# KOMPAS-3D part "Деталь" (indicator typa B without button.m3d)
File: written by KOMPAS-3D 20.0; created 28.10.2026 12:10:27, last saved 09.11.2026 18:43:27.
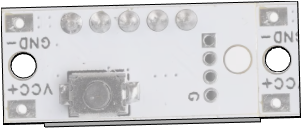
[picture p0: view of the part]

Document properties: Полное имя файла: D:\myProjects\Progect_esp32\box_compas\переключатели и кнопки\indicator typa B without button.m3d

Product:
- Part/product: Деталь
    Масса: 0.00714876

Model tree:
1. Эскиз:1
2. Элемент выдавливания:1
     Расстояние 1 = 1.5
3. Эскиз:2  (with: Элемент выдавливания:1)
4. Элемент выдавливания:2
     Расстояние 2 = 1.5
5. Эскиз:3  (with: Элемент выдавливания:1)
6. Элемент выдавливания:3
     Расстояние 1 = 5.3

Referenced files in D:\RicWork\Project-EPS32\box_compas\переключатели и кнопки\: indicator typa A with button bottom.png, indicator typa B without button top.png
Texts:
  indicator typa A with button bottom.png
  indicator typa B without button top.png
